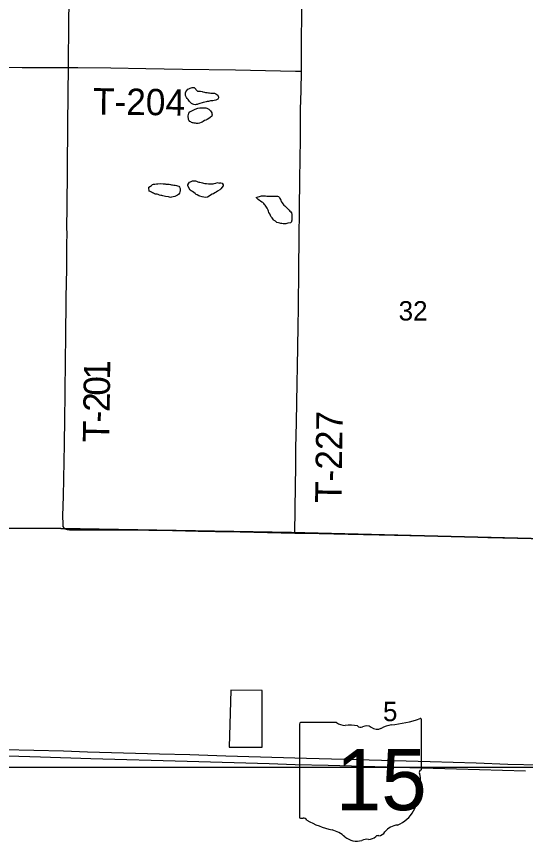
# Model space of a CAD drawing. Extents: x 0 to 68, y 0 to 52.9.
# Drawn here: x 55.298 to 58.195, y 42.989 to 47.729 of the extents above; entities that cross this region are included whole.
import ezdxf

# ---------------------------------------------------------------- set-up
doc = ezdxf.new("R2010")
doc.units = 0
for name, color, linetype in [('Default', 7, 'Continuous'), ('GM_X_Minor_Lake', 7, 'Continuous'), ('GM_X_State_Route', 7, 'Continuous'), ('GM_X_State_Shield', 7, 'Continuous'), ('GM_X_Township', 7, 'Continuous'), ('GM_X_Township_Road', 7, 'Continuous'), ('GM_X_Township_Road_Text', 7, 'Continuous')]:
    doc.layers.add(name, color=color, linetype=linetype)

msp = doc.modelspace()

# ---------------------------------------------------------------- linework, layer by layer
at = {"layer": 'Default'}
msp.add_line((49.5172, 43.4514), (67.9972, 43.4514), dxfattribs=at)
at = {"layer": 'GM_X_Minor_Lake'}
for points in [[(56.3088, 47.3251), (56.3285, 47.3046), (56.3355, 47.3035), (56.3405, 47.3044), (56.3455, 47.3033), (56.3535, 47.3021), (56.3585, 47.301), (56.3675, 47.2978), (56.3725, 47.2967), (56.3785, 47.2956), (56.3835, 47.2955), (56.3905, 47.2944), (56.3965, 47.2942), (56.4045, 47.2931), (56.4115, 47.2929), (56.4236, 47.2927), (56.4315, 47.2895), (56.4384, 47.2844), (56.4434, 47.2803), (56.4472, 47.2702), (56.4471, 47.2651), (56.4439, 47.2582), (56.4368, 47.2543), (56.4318, 47.2534), (56.4227, 47.2516), (56.4157, 47.2497), (56.4096, 47.2488), (56.4026, 47.248), (56.3965, 47.2461), (56.3905, 47.2452), (56.3835, 47.2444), (56.3774, 47.2435), (56.3694, 47.2416), (56.3603, 47.2398), (56.3552, 47.2379), (56.3411, 47.2332), (56.335, 47.2313), (56.33, 47.2294), (56.3249, 47.2285), (56.3199, 47.2276), (56.3149, 47.2267), (56.3069, 47.2288), (56.3009, 47.23), (56.2939, 47.2331), (56.288, 47.2393), (56.2831, 47.2444), (56.2782, 47.2505), (56.2743, 47.2566), (56.2694, 47.2617), (56.2655, 47.2678), (56.2598, 47.2799), (56.2589, 47.288), (56.26, 47.294), (56.2622, 47.301), (56.2663, 47.3069), (56.2725, 47.3148), (56.2786, 47.3177), (56.2857, 47.3205), (56.2917, 47.3224), (56.2968, 47.3243), (56.3028, 47.3252), (56.3058, 47.3252), (56.3088, 47.3251)], [(56.3147, 47.2013), (56.3305, 47.2073), (56.3416, 47.2091), (56.3496, 47.2089), (56.3587, 47.2087), (56.3657, 47.2096), (56.3747, 47.2084), (56.3817, 47.2063), (56.3876, 47.2031), (56.3926, 47.201), (56.4015, 47.1918), (56.4063, 47.1857), (56.4092, 47.1806), (56.4102, 47.1756), (56.411, 47.1686), (56.4089, 47.1616), (56.3997, 47.1538), (56.3926, 47.1489), (56.3834, 47.143), (56.3743, 47.1392), (56.3682, 47.1363), (56.3601, 47.1315), (56.354, 47.1276), (56.3489, 47.1247), (56.3398, 47.1209), (56.3318, 47.12), (56.3268, 47.1201), (56.3217, 47.1202), (56.3157, 47.1213), (56.3087, 47.1215), (56.3037, 47.1226), (56.2987, 47.1237), (56.2938, 47.1258), (56.2888, 47.1289), (56.2838, 47.131), (56.279, 47.1381), (56.2771, 47.1432), (56.2762, 47.1492), (56.2753, 47.1543), (56.2755, 47.1633), (56.2766, 47.1713), (56.2788, 47.1783), (56.284, 47.1862), (56.3147, 47.2013)], [(56.2724, 46.7641), (56.2735, 46.7711), (56.2777, 46.7801), (56.2818, 46.785), (56.2879, 46.7879), (56.2991, 46.7937), (56.3071, 46.7935), (56.3161, 46.7923), (56.3221, 46.7902), (56.3291, 46.7881), (56.336, 46.7859), (56.341, 46.7848), (56.348, 46.7827), (56.356, 46.7815), (56.362, 46.7804), (56.369, 46.7782), (56.379, 46.778), (56.39, 46.7768), (56.403, 46.7756), (56.4121, 46.7764), (56.4171, 46.7763), (56.4221, 46.7772), (56.4322, 46.779), (56.4413, 46.7828), (56.4503, 46.7806), (56.4553, 46.7815), (56.4604, 46.7814), (56.4683, 46.7792), (56.4742, 46.7711), (56.4741, 46.7641), (56.4607, 46.7483), (56.4545, 46.7424), (56.4423, 46.7336), (56.4342, 46.7288), (56.4271, 46.7239), (56.418, 46.7191), (56.4109, 46.7172), (56.4017, 46.7114), (56.3936, 46.7065), (56.3845, 46.6997), (56.3724, 46.6989), (56.3534, 46.7023), (56.3414, 46.7056), (56.3354, 46.7067), (56.3265, 46.7129), (56.3206, 46.716), (56.3147, 46.7212), (56.3067, 46.7263), (56.2988, 46.7325), (56.2919, 46.7367), (56.2859, 46.7398), (56.2724, 46.7641)], [(56.0504, 46.7536), (56.0515, 46.7566), (56.0596, 46.7624), (56.0667, 46.7663), (56.0719, 46.7712), (56.0779, 46.7741), (56.085, 46.7749), (56.094, 46.7758), (56.1011, 46.7756), (56.1161, 46.7773), (56.1322, 46.776), (56.1432, 46.7758), (56.1482, 46.7747), (56.1542, 46.7735), (56.1602, 46.7734), (56.1672, 46.7733), (56.1732, 46.7722), (56.1802, 46.771), (56.1852, 46.7709), (56.1932, 46.7687), (56.2012, 46.7676), (56.2082, 46.7664), (56.2132, 46.7653), (56.2212, 46.7622), (56.2261, 46.756), (56.229, 46.75), (56.2298, 46.7429), (56.2287, 46.7349), (56.2265, 46.73), (56.2244, 46.722), (56.2192, 46.7151), (56.2131, 46.7112), (56.206, 46.7073), (56.1979, 46.7045), (56.1898, 46.7016), (56.1798, 46.6998), (56.1747, 46.6989), (56.1627, 46.7012), (56.1457, 46.7035), (56.1378, 46.7057), (56.1308, 46.7078), (56.1248, 46.7089), (56.1198, 46.71), (56.1118, 46.7122), (56.1038, 46.7154), (56.0978, 46.7165), (56.0928, 46.7166), (56.0878, 46.7177), (56.0829, 46.7198), (56.0779, 46.7219), (56.0709, 46.7251), (56.065, 46.7282), (56.059, 46.7313), (56.0531, 46.7345), (56.0504, 46.7536)], [(56.6623, 46.6971), (56.6916, 46.7075), (56.6986, 46.7074), (56.7047, 46.7073), (56.7097, 46.7072), (56.7157, 46.7071), (56.7217, 46.7059), (56.7277, 46.7058), (56.7377, 46.7056), (56.7488, 46.7054), (56.7588, 46.7062), (56.7658, 46.706), (56.7729, 46.7059), (56.7779, 46.7058), (56.7829, 46.7047), (56.7889, 46.7046), (56.7938, 46.6975), (56.7966, 46.6914), (56.8015, 46.6823), (56.8043, 46.6752), (56.8092, 46.6681), (56.8141, 46.6619), (56.82, 46.6548), (56.8249, 46.6507), (56.8328, 46.6425), (56.8387, 46.6364), (56.8446, 46.6312), (56.8495, 46.6261), (56.8544, 46.621), (56.8593, 46.6159), (56.8632, 46.6098), (56.865, 46.6007), (56.8649, 46.5957), (56.8648, 46.5887), (56.8647, 46.5827), (56.8645, 46.5757), (56.8644, 46.5687), (56.8633, 46.5637), (56.8622, 46.5587), (56.8571, 46.5538), (56.843, 46.551), (56.8359, 46.5492), (56.8309, 46.5483), (56.8238, 46.5484), (56.8158, 46.5486), (56.8078, 46.5497), (56.8028, 46.5508), (56.7958, 46.552), (56.7898, 46.5531), (56.7799, 46.5563), (56.771, 46.5625), (56.765, 46.5666), (56.7601, 46.5708), (56.7562, 46.5759), (56.7523, 46.5819), (56.7454, 46.5901), (56.7425, 46.5962), (56.7387, 46.6043), (56.7348, 46.6124), (56.732, 46.6195), (56.7301, 46.6255), (56.7272, 46.6326), (56.7243, 46.6377), (56.7136, 46.6539), (56.7087, 46.6581), (56.7048, 46.6632), (56.6999, 46.6693), (56.6939, 46.6714), (56.687, 46.6765), (56.6801, 46.6817), (56.6741, 46.6858), (56.6692, 46.6899), (56.6633, 46.6961), (56.6623, 46.6971)], [(56.6959, 43.8887), (56.5171, 43.8909), (56.5079, 43.5652), (56.6967, 43.5663), (56.6959, 43.8887)]]:
    msp.add_lwpolyline(points, dxfattribs=at)
at = {"layer": 'GM_X_State_Route'}
for points in [[(54.6575, 43.5333), (54.6709, 43.5328), (55.0643, 43.5211), (55.433, 43.5101), (55.7199, 43.5015), (56.2691, 43.4862), (56.7362, 43.4724), (56.8837, 43.4676), (57.0723, 43.4628), (57.8017, 43.4415), (58.1951, 43.4298)], [(55.2259, 43.5532), (55.5655, 43.544), (55.7017, 43.5393), (56.1115, 43.5277), (56.2836, 43.523), (56.4884, 43.5169), (56.9475, 43.5033), (57.4478, 43.4892), (57.6528, 43.4833), (57.9144, 43.4756), (58.0953, 43.4695), (58.2762, 43.465)]]:
    msp.add_lwpolyline(points, dxfattribs=at)
at = {"layer": 'GM_X_State_Shield'}
for p, q in [((57.1187, 43.7067), (56.9149, 43.7067)), ((57.6041, 43.4434), (57.6041, 43.7198)), ((56.908, 43.6976), (56.908, 43.1693)), ((57.604, 43.4435), (57.6041, 43.4434))]:
    msp.add_line(p, q, dxfattribs=at)
for centre, radius, start, end in [((56.916, 43.6987), 0.00806, 98.1301, 188.1301), ((57.1673, 43.768), 0.0782, 231.6195, 271.1119), ((57.3561, 44.427), 0.7382, 275.8445, 288.9065), ((57.5964, 43.7209), 0.00775, 351.8621, 97.738), ((57.1932, 43.4101), 0.2808, 80.4867, 94.9883), ((57.2569, 43.7015), 0.0226, 219.7921, 297.1024), ((57.2901, 43.6404), 0.0469, 54.4667, 119.1411), ((57.3506, 43.7242), 0.0564, 233.8562, 294.8282), ((57.4503, 43.5453), 0.1485, 97.3462, 120.7689), ((57.6023, 43.4231), 0.012, 107.944, 210.337), ((57.526, 43.3882), 0.072, 340.033, 23.6496), ((57.5958, 43.4423), 0.00829, 289.6038, 7.7341), ((57.6319, 43.3278), 0.0524, 136.8065, 186.9296), ((57.3975, 43.2926), 0.1846, 292.3089, 8.9858), ((56.9161, 43.1681), 0.00814, 171.9584, 258.3066), ((56.9173, 43.2222), 0.0621, 267.339, 280.6039), ((56.93, 43.1388), 0.0224, 29.7484, 93.2717), ((57.2126, 43.6135), 0.5331, 240.4129, 257.1985), ((57.0537, 42.9319), 0.1668, 47.1842, 75.836), ((57.4753, 43.021), 0.1011, 94.4031, 142.5768), ((57.2341, 43.1362), 0.1058, 230.7004, 286.2918), ((57.2952, 42.9535), 0.087, 85.6951, 111.2099), ((57.303, 43.0966), 0.0564, 268.777, 315.5493), ((57.354, 43.0455), 0.0159, 65.7517, 132.6484), ((57.3472, 43.1181), 0.0597, 282.8732, 323.2771)]:
    msp.add_arc(centre, radius, start, end, dxfattribs=at)
at = {"layer": 'GM_X_Township'}
for points in [[(58.8342, 44.7404), (56.8623, 44.7881), (55.55, 44.811), (53.9477, 44.8207), (53.9362, 44.8202), (53.5717, 44.8269), (53.5816, 45.1755), (53.5859, 45.2978), (53.5861, 45.3128), (53.6079, 46.1573), (53.6232, 46.7171), (53.6354, 47.2484), (53.6343, 47.3192), (53.6375, 47.4454), (53.638, 47.5748), (53.6422, 47.7406)], [(53.4359, 34.4614), (53.475, 36.9167), (53.476, 36.9822), (53.4921, 38.2302), (53.493, 38.2977), (53.5163, 39.5532), (53.5177, 39.6161), (53.5297, 40.9525), (53.5453, 42.2102), (53.554, 42.96), (53.5575, 43.4417), (53.5653, 43.7753), (53.5564, 43.9111), (53.5572, 43.9542), (53.5711, 44.5876), (53.5712, 44.6417), (53.5717, 44.8269), (53.9362, 44.8202), (53.9477, 44.8207), (55.55, 44.811), (56.8623, 44.7881), (58.8342, 44.7404)]]:
    msp.add_lwpolyline(points, dxfattribs=at)
at = {"layer": 'GM_X_Township_Road'}
for points in [[(56.9192, 47.4172), (56.9194, 47.4374), (56.92, 47.5848), (56.921, 47.7489), (56.9225, 47.9376), (56.9223, 48.0267), (56.9228, 48.1079), (56.9228, 48.113)], [(55.6169, 47.932), (55.6096, 47.8847), (55.5997, 47.8117), (55.5955, 47.771), (55.5937, 47.7383), (55.5932, 47.7055), (55.5907, 47.4384)], [(55.0625, 47.4422), (55.33, 47.4396), (55.5324, 47.4388), (55.5907, 47.4384)], [(55.5907, 47.4384), (55.5889, 47.2935), (55.5874, 47.1048), (55.5828, 46.6291), (55.5823, 46.5402), (55.5831, 46.4782), (55.5824, 46.4472), (55.5808, 46.2919), (55.5785, 46.1283), (55.5767, 45.8906), (55.5746, 45.7839), (55.5723, 45.5707), (55.5699, 45.4394), (55.5676, 45.2918), (55.5619, 44.9965), (55.559, 44.8843), (55.5599, 44.836), (55.5604, 44.8283), (55.5617, 44.8228), (55.5672, 44.8158)], [(55.5907, 47.4384), (55.6459, 47.4384), (55.8336, 47.4371), (56.0332, 47.4336), (56.2427, 47.43), (56.5439, 47.4247), (56.8859, 47.4174), (56.9192, 47.4172)], [(56.8815, 44.7858), (56.8854, 45.0558), (56.8874, 45.1624), (56.8885, 45.269), (56.892, 45.4166), (56.8934, 45.5315), (56.8992, 45.8431), (56.901, 45.9662), (56.903, 46.0646), (56.9055, 46.2942), (56.907, 46.4665), (56.9086, 46.6303), (56.911, 46.8019), (56.9134, 47.0311), (56.9146, 47.1131), (56.9152, 47.2022), (56.9179, 47.3064), (56.9192, 47.4172)], [(55.5672, 44.8158), (55.5744, 44.8092), (55.5855, 44.8052), (55.5983, 44.804), (55.6155, 44.804), (55.6556, 44.8045), (55.7373, 44.8036), (55.9137, 44.8032), (56.1844, 44.8005), (56.332, 44.7965), (56.4304, 44.7954), (56.5698, 44.7926), (56.8815, 44.7858)], [(56.8815, 44.7858), (57.0209, 44.7825), (57.1849, 44.7792), (57.5376, 44.772), (57.8821, 44.7641), (57.9805, 44.7614), (58.2347, 44.7554), (58.4479, 44.7502), (58.6448, 44.7456), (58.8088, 44.7419), (58.8301, 44.7413)]]:
    msp.add_lwpolyline(points, dxfattribs=at)

# ---------------------------------------------------------------- texts
at = {"layer": 'Default'}
for s, p in [('32', (57.4732, 45.997)), ('5', (57.3841, 43.7136))]:
    msp.add_text(s, height=0.1105, rotation=0, dxfattribs=at).set_placement(p)
at = {"layer": 'GM_X_State_Shield'}
msp.add_text('15', height=0.34805, dxfattribs=at).set_placement((57.1153, 43.2065))
at = {"layer": 'GM_X_Township_Road_Text'}
for s, rotation, p in [('T-204', 359.2261, (55.7317, 47.1717)), ('1', 89.3234, (55.8298, 45.6595)), ('0', 89.3038, (55.8287, 45.5678)), ('2', 89.031, (55.8271, 45.4754)), ('-', 89.0088, (55.826, 45.4143)), ('T-227', 89.1595, (57.1472, 44.9562)), ('T', 89.1131, (55.8243, 45.3024))]:
    msp.add_text(s, height=0.15, rotation=rotation, dxfattribs=at).set_placement(p)

doc.saveas('drawing.dxf')
